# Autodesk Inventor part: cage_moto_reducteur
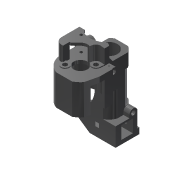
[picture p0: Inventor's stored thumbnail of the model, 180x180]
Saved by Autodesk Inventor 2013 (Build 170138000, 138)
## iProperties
Created: 2011-07
Part Number: cage_moto_reducteur
Document SubType Name: Modeling
Designer: didierf
Density: 1.13 g/cm^3
Material: Nylon - 6/6
Mass: 1.97671 g
Surface Area: 29.4498 cm^2
Volume: 1.7493 cm^3
entraxe_moteur_mobile: 6,000 mm
entraxe_mobile_roue_vis: 7,950 mm
entraxe_moteur_roue_vis: 12,000 mm
Author: didierf
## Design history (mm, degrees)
sketch "Esquisse1" dims "d1" = 12 (= 2 x entraxe_moteur_mobile), "d3" = 15.9 (= 2 x entraxe_mobile_roue_vis), "d4" = 24 (= 2 x entraxe_moteur_roue_vis)
  geometry: C1 r 2.5 at (2.847, -0.387); C2 r 0.5 at (-1.852, 3.344); C3 r 3.14 at (-9.14, 0.167); 3 further points
  constraints: 3 centre point, 3 coincident, 9 other
  dimensions: "d0" = 5 diameter of C1; "d2" = 1 diameter of C2; "d5" = 6.28 diameter of C3
sketch "Esquisse2" dims "d66" = 15.9 (= 2 x entraxe_mobile_roue_vis), "d67" = 12 (= 2 x entraxe_moteur_mobile), "d68" = 24 (= 2 x entraxe_moteur_roue_vis)
  geometry: L1 (-154.32, -14.987)-(-180.391, -5.63); L2 (-180.391, -5.63)-(-170.126, 22.971); L3 (-170.126, 22.971)-(-144.055, 13.613); L4 (-144.055, 13.613)-(-154.32, -14.987); L5 (-31.79, 28.076)-(-25.53, 28.076); L6 (-25.53, 28.076)-(-25.53, 27.076); L7 (-25.53, 27.076)-(-31.79, 27.076); L8 (-31.79, 27.076)-(-31.79, 28.076); L9 (-31.79, 28.076)-(-25.53, 27.076); L10 (-24.13, 32.056)-(-24.13, 23.306); L11 (-32.96, 32.056)-(-32.96, 23.306); L12 (-28.66, 27.576)-(-28.66, 30.706); L13 (-29.16, 24.446)-(-29.16, 30.706); L14 (-29.16, 30.706)-(-28.66, 30.706); L15 (-32.96, 32.056)-(-24.13, 32.056); L16 (-32.96, 23.306)-(-24.13, 23.306); L17 (-19.93, 38.152)-(-19.93, 8.926); L18 (-33.93, 33.977)-(-33.93, 8.926); L19 (-33.93, 8.926)-(-19.93, 8.926); L20 (-67.292, 19.43)-(-62.292, 19.43); L21 (-62.292, 19.43)-(-62.292, 18.43); L22 (-62.292, 18.43)-(-67.292, 18.43); L23 (-67.292, 18.43)-(-67.292, 19.43); L24 (-67.292, 19.43)-(-62.292, 18.43); L25 (-29.16, 24.446)-(-27.655, 24.446); C1 r 2.5 at (-60.831, 26.959); C2 r 0.5 at (-31.23, 20.052); C3 r 2.5 at (-27.128, 15.674); A1 r 3.17 centre (-28.66, 27.576) between (-31.79, 27.076) and (-29.16, 30.706); 4 further points
  constraints: 42 end point, 10 parallel, 7 perpendicular, 4 centre point, 3 coincident, 3 point on circle, 2 horizontal, 2 midpoint, 14 other
  dimensions: "d7" = 27.7 distance of L2.end L3.end; "d46" = 1 distance of L7.end L5.start; "d47" = 6.26 distance of L5.start L5.end; "d48" = 1.4 distance between parallel lines of L10 L6; "d49" = 8.83 distance between parallel lines of L11 L10; "d50" = 0.5 distance between parallel lines of L12 L13; "d51" = 1.35 distance between parallel lines of L15 L14; "d54" = 8.75 distance between parallel lines of L16 L15; "d55" = 4.2 distance between parallel lines of L17 L10; "d56" = 14 distance between parallel lines of L18 L17; "d58" = 23.13 distance between parallel lines of L19 L15; "d63" = 5 diameter of C1; "d64" = 5 distance of L21.end L22.end; "d65" = 1 distance of L20.end L21.end; "d69" = 2.7 distance from line of L18 C2.centre; "d275" = 5 diameter of C3; "d277" = 1 diameter of C2
  node "Image1"
sketch "Esquisse3"
  geometry: L1 (-32.96, 32.056)-(-24.13, 32.056) reference; L2 (-32.96, 32.056)-(-32.96, 23.306) reference; L3 (-32.96, 23.306)-(-24.13, 23.306) reference; L4 (-24.13, 32.056)-(-24.13, 23.306) reference
  dimensions: "d73" = 8.83 distance of L1.start L1.end (derived); "d74" = 8.75 distance of L1.start L2.end (derived)
extrude "corps_vis" new body sketch "Esquisse3" distance "d71" = 25.84; taper "d72" = 0 deg
sketch "Esquisse4"
  geometry: C1 r 3.175 at (-28.66, 27.576) reference
extrude "alésage roulements" cut sketch "Esquisse4" distance "d75" = 16.9; taper "d76" = 0 deg
sketch "Esquisse5"
  geometry: L1 (-24.13, 32.056)-(-24.13, 23.306) reference; L2 (-32.96, 32.056)-(-24.13, 32.056) reference; L3 (-32.96, 23.306)-(-32.96, 32.056) reference; L4 (-24.13, 23.306)-(-32.96, 23.306) reference; C1 r 3.17 at (-28.66, 27.576); C2 r 3 at (-28.66, 27.576); C3 r 3.175 at (-28.66, 27.576) reference
  constraints: 2 centre point, 1 coincident
  dimensions: "d289" = 6 diameter of C2
extrude "alésage butée roul" cut sketch "Esquisse5" distance "d79" = 19; taper "d80" = 0 deg
sketch "Esquisse6"
  geometry: L1 (-24.13, 32.056)-(-24.13, 23.306) reference; L2 (-32.96, 32.056)-(-24.13, 32.056) reference; L3 (-32.96, 23.306)-(-32.96, 32.056) reference; L4 (-24.13, 23.306)-(-32.96, 23.306) reference; C1 r 3.17 at (-28.66, 27.576); C2 r 1.98 at (-28.66, 27.576); C3 r 3.175 at (-28.66, 27.576) reference
  constraints: 2 centre point, 1 coincident
  dimensions: "d81" = 3.96 diameter of C2
extrude "alésage extrem vis" cut sketch "Esquisse6" stored distance "d82" = 19; taper "d83" = 0 deg
sketch "Esquisse9"
  geometry: L1 (0, 0)-(0, 25.84) reference; L2 (0, 25.84)-(0, 27.34); L3 (0, 27.34)-(-4, 27.34); L4 (-4, 27.34)-(-4, 0); L5 (0, 0)-(-4, 0)
  constraints: 8 end point, 2 perpendicular, 1 collinear, 1 parallel
  dimensions: "d91" = 4 distance between parallel lines of L4 L2; "d92" = 27.34 distance between parallel lines of L3 L5
extrude "platine_fixation" join sketch "Esquisse9" distance "d93" = 4; taper "d94" = 0 deg
sketch "Esquisse10"
  geometry: L1 (12.83, 0)-(4, 0) reference; L2 (2.832, -7.632)-(2.832, 0); L3 (16.832, -7.632)-(16.832, -2.75); L4 (7.552, -14.25)-(13.36, -14.25); L5 (4, 8.75)-(12.83, 8.75) reference; L6 (12.83, 8.75)-(12.83, 0) reference; L7 (12.83, 0)-(12.83, -0.757); L8 (16.832, -2.75)-(15.032, -2.75); L9 (15.032, -2.75)-(15.032, -2.227); L10 (4, 0)-(2.832, 0); L11 (9.832, -7.632)-(20.481, -7.632); L12 (16.832, -7.632)-(15.742, -12.25); C1 r 2.5 at (9.832, -7.632) reference; A1 r 7.5 centre (9.832, -7.632) between (13.36, -14.25) and (15.742, -12.25); A2 r 7 centre (9.832, -7.632) between (2.832, -7.632) and (7.552, -14.25); A3 r 7.5 centre (9.832, -7.632) between (15.032, -2.227) and (12.83, -0.757)
  constraints: 18 end point, 6 point on circle, 3 centre point, 3 perpendicular, 2 collinear, 2 parallel, 1 coincident, 1 point on line, 1 tangent
  dimensions: "d96" = 14 distance between parallel lines of L3 L2; "d97" = 23 distance between parallel lines of L4 L5; "d99" = 7.5 radius of A1; "d100" = 7 radius of A2; "d102" = 11.5 distance between parallel lines of L8 L4; "d103" = 7.5 radius of A3; "d104" = 1.8 distance between parallel lines of L3 L9; "d108" = 2 distance from line of L12.end L4
extrude "cage moteur" join sketch "Esquisse10" distance "d105" = 11.2; taper "d106" = 0 deg
sketch "Esquisse11" dims "d126" = 8
  geometry: L1 (5.232, -14.032)-(5.832, -14.032); L2 (5.832, -14.032)-(5.832, -11.632); L3 (5.832, -11.632)-(2.832, -11.632); L4 (2.832, -11.632)-(2.832, -14.032); L5 (14.332, -5.632)-(14.332, -7.321); L6 (15.032, -6.75)-(15.032, -6.227); L7 (7.552, -18.25)-(13.36, -18.25); L8 (16.832, -11.632)-(16.832, -6.75); L9 (2.832, -4)-(2.832, -11.632); L10 (5.832, -11.632)-(2.832, -11.632); L11 (12.83, -4.757)-(12.83, -4); L12 (9.832, -11.632)-(12.661, -8.803); L13 (12.834, -7.163)-(14.332, -7.321); L14 (9.773, -6.573)-(10.012, -9.138); L15 (11.045, -8.469)-(10.862, -9.354); L16 (4, 0)-(0, 0) reference; L17 (0, -4)-(0, 0) reference; L18 (2.832, -4)-(0, -4) reference; L19 (2.832, -4)-(2.832, -11.632) reference; L20 (7.552, -18.25)-(13.36, -18.25) reference; L21 (15.742, -16.25)-(16.832, -11.632) reference; L22 (16.832, -11.632)-(16.832, -6.75) reference; L23 (16.832, -6.75)-(15.032, -6.75) reference; L24 (15.032, -6.75)-(15.032, -6.227) reference; L25 (12.83, -4.757)-(12.83, -4) reference; L26 (12.83, -4)-(4, -4) reference; L27 (4, -4)-(4, 0) reference; C1 r 3.17 at (8.3, 0.27); C2 r 0.906 at (-111.833, -48.822); C3 r 0.735 at (-104.635, -44.629); C4 r 2.5 at (9.832, -11.632) reference; A1 r 2.4 centre (5.232, -11.632) between (2.832, -11.632) and (5.232, -14.032); A2 r 7.5 centre (9.832, -11.632) between (15.032, -6.227) and (12.83, -4.757); A3 r 1.65 centre (12.661, -8.803) between (12.834, -7.163) and (11.045, -8.469); A4 r 7 centre (9.832, -11.632) between (2.832, -11.632) and (5.832, -17.376); A5 r 7 centre (8.3, 0.27) between (9.773, -6.573) and (13.06, -4.862); A6 r 7.5 centre (9.832, -11.632) between (14.332, -5.632) and (13.06, -4.862); A7 r 2.5 centre (9.832, -11.632) between (10.012, -9.138) and (10.862, -9.354); A8 r 2.5 centre (9.832, -11.632) between (10.862, -9.354) and (10.012, -9.138); A9 r 7 centre (9.832, -11.632) between (2.832, -11.632) and (7.552, -18.25) reference; A10 r 7.5 centre (9.832, -11.632) between (13.36, -18.25) and (15.742, -16.25) reference; A11 r 7.5 centre (9.832, -11.632) between (15.032, -6.227) and (12.83, -4.757) reference
  constraints: 32 end point, 17 point on circle, 11 centre point, 5 coincident, 2 parallel, 2 perpendicular, 2 point on line, 2 tangent, 1 collinear, 1 horizontal, 3 other
  dimensions: "d114" = 2.5 distance between parallel lines of L8 L5; "d116" = 0 distance between parallel lines of L4 L9; "d117" = 3 distance of L2.end L3.end; "d118" = 2.4 distance of L3.end L4.end; "d119" = 2.4 distance between parallel lines of L10 L1; "d120" = 2.4 radius of A1; "d124" = 4.21821 distance between parallel lines of L1 L7; "d128" = 45 deg angle of L8 L12; "d129" = 3.3 diameter of A3; "d143" = 14 diameter of A5; "d144" = 1.68908 distance of L5.start L5.end
extrude "piliers" join sketch "Esquisse11" distance "d122" = 4.5; taper "d123" = 0 deg
sketch "Esquisse12"
  geometry: L1 (5.832, -11.632)-(6.332, -11.632); L2 (14.332, -7.321)-(12.834, -7.163) reference; L3 (5.832, -14.032)-(5.232, -14.032) reference; L4 (2.832, -11.632)-(2.832, -5.032); L5 (2.832, -5.032)-(4.832, -5.032); L6 (5.832, -11.632)-(5.832, -14.032) reference; L7 (14.332, -7.321)-(14.332, -5.632); L8 (6.332, -11.632)-(8.046, -9.882); L9 (13.06, -4.862)-(14.332, -5.632); L10 (11.045, -8.469)-(10.862, -9.354) reference; C1 r 3.17 at (8.3, 0.27) reference; A1 r 2.4 centre (5.232, -11.632) between (2.832, -11.632) and (5.232, -14.032) reference; A2 r 1.65 centre (12.661, -8.803) between (12.834, -7.163) and (11.045, -8.469) reference; A3 r 7 centre (8.3, 0.27) between (9.773, -6.573) and (13.06, -4.862) reference; A4 r 7 centre (8.3, 0.27) between (6.139, -6.388) and (13.06, -4.862); A5 r 7.5 centre (9.832, -11.632) between (14.332, -5.632) and (13.06, -4.862) reference; A6 r 2 centre (6.756, -4.486) between (4.832, -5.032) and (6.139, -6.388); A7 r 2.5 centre (9.832, -11.632) between (10.862, -9.354) and (10.012, -9.138) reference; A8 r 2.5 centre (9.832, -11.632) between (10.862, -9.354) and (8.046, -9.882); 1 further point
  constraints: 13 end point, 9 point on circle, 3 centre point, 3 tangent, 2 coincident, 1 horizontal, 1 parallel, 1 perpendicular, 1 point on line
  dimensions: "d133" = 0.5 distance of L1.start L1.end; "d137" = 9 distance between parallel lines of L5 L3; "d147" = 2 radius of A6; "d148" = 2 distance of L4.end L5.end
extrude "platine" join sketch "Esquisse12" distance "d138" = 1; taper "d139" = 0 deg
sketch "Esquisse14"
  geometry: L1 (-27.34, 0)-(-25.84, 0) reference; L2 (-25.84, 8.75)-(-25.84, 0) reference; L3 (-27.34, 0)-(-25.84, 1.1)
  constraints: 2 end point, 1 point on line
  dimensions: "d153" = 1.1 vertical distance of L1.start L3.end
extrude "chanfrein" join sketch "Esquisse14" stored distance "d154" = 1; taper "d155" = 0 deg
sketch "Esquisse13"
  geometry: L1 (0, 0)-(11.2, 0) reference; L2 (0, 0)-(0, 0.523) reference; L3 (1.5, 11.5)-(1.5, 3.85) reference; L4 (0, 0.523)-(11.2, 0.523) reference; L5 (4.45, 0.523)-(1.55, 0.523); L6 (4.45, 2.1)-(4.45, 0.523); L7 (4.45, 0)-(4.45, -0.154); L8 (1.55, 2.1)-(1.55, 0.523); L9 (1.05, 0)-(1.05, -0.345); L10 (27.34, 11.5)-(1.5, 11.5) reference; L11 (27.34, 11.5)-(27.34, 2.75) reference; L12 (27.34, 2.75)-(11.2, 2.75) reference; L13 (20.54, 2.75)-(20.54, 7.85); L14 (19.5, 7.85)-(20.54, 7.85); L15 (25.19, 10.75)-(19.5, 10.75); L16 (20.54, 2.75)-(27.34, 2.75); L17 (27.34, 2.75)-(27.34, 10.75); L18 (25.19, 10.75)-(25.19, 11.5); L19 (25.19, 11.5)-(27.34, 11.5); L20 (27.34, 11.5)-(27.34, 10.75); C1 r 0.9 at (3, 2.1); C2 r 0.9 at (19.5, 9.3); A1 r 1.45 centre (3, 2.1) between (4.45, 2.1) and (1.55, 2.1); A2 r 1.45 centre (19.5, 9.3) between (19.5, 10.75) and (19.5, 7.85)
  constraints: 26 end point, 8 point on line, 7 parallel, 5 point on circle, 5 tangent, 4 centre point, 4 collinear, 3 perpendicular, 2 coincident
  dimensions: "d149" = 2.1 distance from line of A1.centre L1; "d151" = 2.9 diameter of A1; "d152" = 1.8 diameter of C1; "d156" = 1.5 distance from line of L3 C1.centre; "d159" = 16.5 horizontal distance of C1.centre C2.centre; "d161" = 1.8 diameter of C2; "d162" = 6.8 distance between parallel lines of L13 L11; "d163" = 0.75 distance between parallel lines of L15 L10; "d164" = 1.45 radius of A2; "d263" = 2.15 distance between parallel lines of L20 L18
extrude "bossages" join sketch "Esquisse13" stored distance "d157" = 1; taper "d158" = 0 deg
sketch "Esquisse15"
  geometry: C1 r 0.8 at (3, 2.1); C2 r 0.8 at (19.5, 9.3); A1 r 1.45 centre (19.5, 9.3) between (19.5, 10.75) and (19.5, 7.85) reference; A2 r 1.45 centre (3, 2.1) between (4.45, 2.1) and (1.55, 2.1) reference
  constraints: 2 centre point, 2 coincident
  dimensions: "d165" = 1.6 diameter of C2; "d166" = 1.6 diameter of C1 (derived)
extrude "perçage bossage" cut sketch "Esquisse15" distance "d167" = 3; taper "d168" = 0 deg
sketch "Esquisse17"
  geometry: L1 (11.2, -2.618)-(2, -2.618); L2 (2, -2.618)-(2, 1.882); L3 (2, 1.882)-(11.2, 1.882); L4 (11.2, 1.882)-(11.2, -2.618); L5 (0, -6.618)-(11.2, -6.618) reference; L6 (0, 0)-(0, 4.882) reference; L7 (11.2, 0)-(11.2, 4.882) reference
  constraints: 8 end point, 2 parallel, 1 collinear, 1 horizontal, 1 perpendicular
  dimensions: "d172" = 4 distance between parallel lines of L5 L1; "d173" = 4.5 distance of L3.end L1.start; "d174" = 2 distance between parallel lines of L2 L6
extrude "fenetre log moteur" cut sketch "Esquisse17" distance "d175" = 5; taper "d176" = 0 deg
sketch "Esquisse16"
  geometry: C1 r 2.5 at (-9.832, -7.632) reference; C2 r 6.25 at (-9.832, -7.632)
  constraints: 1 centre point, 1 coincident
  dimensions: "d169" = 12.5 diameter of C2
extrude "log moteur" cut sketch "Esquisse16" distance "d170" = 10; taper "d171" = 0 deg
sketch "Esquisse18"
  geometry: L1 (-12.83, 8.75)-(-12.83, 1.1); L2 (-12.83, 1.1)-(-12.83, 0); L3 (-12.83, -0.757)-(-12.83, 0); L4 (-12.83, -0.757)-(-12.83, -0.75); L5 (-12.83, -0.75)-(-12.83, -0.75); L6 (-12.83, -0.75)-(-12.83, -0.757); L7 (-12.83, -0.757)-(-12.83, 0); L8 (-12.83, 0)-(-12.83, 5.1); L9 (-12.83, 5.1)-(-12.83, 8); L10 (-12.83, 0)-(-2.832, 0); L11 (-12.83, 8)-(-12.83, 8.75); L12 (-15.507, -10.25)-(-16.214, -10.25) reference; L13 (-15.742, -12.25)-(-16.214, -10.25) reference; L14 (-7.552, -14.25)-(-13.36, -14.25) reference; L15 (-2.832, 0)-(-2.832, -7.632) reference; L16 (-12.83, 0)-(-2.832, 0) reference; L17 (-12.83, -0.757)-(-12.83, 0) reference; L18 (-15.032, -2.75)-(-15.032, -2.227) reference; L19 (-16.832, -2.75)-(-15.032, -2.75) reference; L20 (-16.832, -5.75)-(-16.832, -2.75) reference; L21 (-16.832, -5.75)-(-15.792, -5.75) reference; C1 r 3.17 at (-8.3, 4.27); A1 r 4.75 centre (-8.3, 4.27) between (-12.83, 2.841) and (-10.381, 0); A2 r 6.25 centre (-9.832, -7.632) between (-15.507, -10.25) and (-15.792, -5.75) reference; A3 r 7.5 centre (-9.832, -7.632) between (-15.742, -12.25) and (-13.36, -14.25) reference; A4 r 7 centre (-9.832, -7.632) between (-7.552, -14.25) and (-2.832, -7.632) reference; A5 r 7.5 centre (-9.832, -7.632) between (-12.83, -0.757) and (-15.032, -2.227) reference
  constraints: 22 end point, 2 centre point, 2 point on circle, 2 point on line, 1 coincident
extrude "forme extrne 1" cut sketch "Esquisse18" stored distance "d178" = 5; taper "d179" = 0 deg
node "Plan de construction2"
sketch "Esquisse19"
  geometry: L1 (-1.168, -27.34)-(-4, -27.34) reference; L2 (-4, -27.34)-(-4, 0) reference; L3 (11.032, 0)-(-4, 0) reference; L4 (-5.57, -14.935)-(17.224, -14.935); L5 (8.83, -16.14)-(8.83, -6.8) reference; L6 (3.43, -6.833)-(3.43, -13.539); L7 (-4, -4.84)-(-4, -25.34); L8 (-3.129, -3.189)-(1.532, 0); L9 (1.532, 0)-(-4, 0); L10 (-4, -25.34)-(-4, -27.34); L11 (-4, -27.34)-(-2, -27.34); A1 r 2 centre (-2, -25.34) between (-2.649, -23.448) and (-2, -27.34); A2 r 2 centre (-2, -4.84) between (-1.688, -6.816) and (-3.484, -6.18); A3 r 9 centre (-5.57, -14.935) between (-2.649, -23.448) and (-3.484, -6.18)
  constraints: 14 end point, 10 point on circle, 8 tangent, 4 point on line, 3 centre point, 2 collinear, 2 parallel, 1 perpendicular
  dimensions: "d181" = 4 diameter of A1; "d182" = 4 diameter of A2; "d183" = 18 diameter of A3; "d184" = 20.5 distance of A2.centre A1.centre; "d185" = 5.4 distance between parallel lines of L6 L5; "d186" = 9.5 distance of L3.start L8.end
extrude "debouchage engrenage" cut sketch "Esquisse19" stored distance "d187" = 5; taper "d188" = 0 deg; taper "d254" = 0 deg
sketch "Esquisse22"
  geometry: L1 (0, -27.34)-(-2, -27.34) reference; L2 (0, -25.84)-(0, -27.34) reference; L3 (0, -22.005)-(0, -25.84) reference; L4 (0, -1.048)-(0, -7.866) reference; L5 (0, -1.048)-(-3.129, -3.189) reference; A1 r 9 centre (-5.57, -14.935) between (-2.649, -23.448) and (0, -22.005) reference; A2 r 2 centre (-2, -25.34) between (-2.649, -23.448) and (-2, -27.34) reference; A3 r 9 centre (-5.57, -14.935) between (0, -7.866) and (-3.484, -6.18) reference; A4 r 2 centre (-2, -4.84) between (-3.129, -3.189) and (-3.484, -6.18) reference
extrude "correction" cut sketch "Esquisse22" distance "d191" = 0.7; taper "d192" = 0 deg
sketch "Esquisse23"
  geometry: C1 r 1.7 at (-2, -25.34); C2 r 1.7 at (-2, -4.84); A1 r 2 centre (-2, -25.34) between (-2.649, -23.448) and (-2, -27.34) reference; A2 r 2 centre (-2, -4.84) between (-3.129, -3.189) and (-3.484, -6.18) reference
  constraints: 2 centre point, 2 coincident
  dimensions: "d193" = 3.4 diameter of C1; "d194" = 3.4 diameter of C2
extrude "bossages2" join sketch "Esquisse23" distance "d195" = 1; taper "d196" = 0 deg
sketch "Esquisse24"
  geometry: C1 r 1.7 at (0, 0) reference; C2 r 1.7 at (0, 20.5) reference; C3 r 1 at (0, 0); C4 r 1 at (0, 20.5)
  constraints: 2 centre point, 2 coincident
  dimensions: "d197" = 2 diameter of C3; "d198" = 2 diameter of C4
extrude "trous bossages2" cut sketch "Esquisse24" stored distance "d199" = 1; taper "d200" = 0 deg
sketch "Esquisse25"
  geometry: A1 r 9 centre (-3.57, -9.995) between (-0.084, -1.698) and (-1.011, -1.367) reference; A2 r 1.7 centre (0, 0) between (-0.084, -1.698) and (-1.011, -1.367) reference
extrude "correction2" cut sketch "Esquisse25" stored distance "d201" = 1; taper "d202" = 0 deg
sketch "Esquisse27"
  geometry: L1 (-32.96, 26.606)-(-32.96, 32.056); L2 (-32.96, 32.056)-(-24.13, 32.056); L3 (-32.96, 30.127)-(-32.96, 32.056); L4 (-32.96, 32.056)-(-30.88, 32.056); L5 (-32.96, 24.406)-(-28.838, 24.406) reference; L6 (-28.482, 24.406)-(-24.13, 24.406) reference; L7 (-24.13, 32.056)-(-24.13, 24.406) reference; L8 (-32.96, 32.056)-(-24.13, 32.056) reference; L9 (-32.96, 26.606)-(-32.96, 32.056) reference; L10 (-32.96, 24.406)-(-32.96, 26.606) reference; C1 r 3.17 at (-28.66, 27.576); A1 r 5 centre (-28.66, 27.576) between (-32.96, 30.127) and (-30.88, 32.056); A2 r 3.175 centre (-28.66, 27.576) between (-28.482, 24.406) and (-28.838, 24.406) reference
  constraints: 8 end point, 2 centre point, 2 point on circle, 2 point on line, 1 coincident, 1 collinear
  dimensions: "d210" = 10 diameter of A1
extrude "forme externe 2" cut sketch "Esquisse27" stored distance "d211" = 10; taper "d212" = 0 deg
node "Plan de construction3"
node "Plan de construction6"
sketch "Esquisse26"
  geometry: L1 (-30.88, 32.056)-(-24.13, 32.056); L2 (-32.96, 26.606)-(-32.96, 30.127); L3 (-27.081, 32.056)-(-24.13, 32.056); L4 (-24.13, 32.056)-(-24.13, 29.004); C1 r 3.17 at (-28.66, 27.576); A1 r 4.75 centre (-28.66, 27.576) between (-24.13, 29.004) and (-27.081, 32.056); 1 further point
  constraints: 8 end point, 2 centre point, 2 point on circle, 1 coincident, 1 collinear, 1 perpendicular, 1 point on line
  dimensions: "d206" = 9.5 diameter of A1
extrude "forme externe 3" cut sketch "Esquisse26" stored distance "d213" = 10; taper "d214" = 0 deg
sketch "Esquisse29"
  geometry: L1 (-30.88, 32.056)-(-24.13, 32.056) reference; L2 (-24.13, 32.056)-(-24.13, 24.406) reference; L3 (-24.13, 32.056)-(-26.12, 32.056); L4 (-24.13, 32.056)-(-24.13, 30.025); C1 r 3.17 at (-28.66, 27.576) reference; A1 r 4.75 centre (-28.66, 27.576) between (-24.13, 29.004) and (-27.081, 32.056) reference; A2 r 5.15 centre (-28.66, 27.576) between (-24.13, 30.025) and (-26.12, 32.056)
  constraints: 4 end point, 2 point on circle, 2 point on line, 1 centre point, 1 coincident
  dimensions: "d217" = 0.4 radial gap between concentric circles of A2 A1
extrude "forme externe 4" cut sketch "Esquisse29" stored distance "d218" = 18; taper "d219" = 0 deg
sketch "Esquisse30"
  geometry: L1 (2.48, 0)-(1.822, 0) reference; L2 (1.04, 1.28)-(0, 1.28) reference; L3 (0, 1.28)-(0, 0) reference; L4 (0.258, 0)-(0, 0) reference; A1 r 1.45 centre (1.04, -0.17) between (2.48, 0) and (1.04, 1.28) reference; A2 r 0.8 centre (1.04, -0.17) between (1.822, 0) and (0.258, 0) reference
extrude "bouchage forme externe 4" join sketch "Esquisse30" stored distance "d221" = 18; taper "d222" = 0 deg
sketch "Esquisse31"
  geometry: C1 r 1.7 at (-4.08, -25.34) reference; 2 further points
  constraints: 1 coincident, 3 other
extrude "marque éject" cut sketch "Esquisse31" stored distance "d224" = 18; taper "d225" = 0 deg
sketch "Esquisse32"
  geometry: L1 (0.784, -25.84)-(0, -25.84) reference; L2 (0, -27.34)-(-2, -27.34) reference; L3 (0, -25.84)-(-0.064, -25.84); L4 (0, -27.34)-(0, -25.84); L5 (0, -27.34)-(-2, -27.34); A1 r 2.828 centre (-2, -25.34) between (0.784, -25.84) and (0, -23.34) reference; A2 r 2 centre (-2, -25.34) between (-2, -27.34) and (-0.064, -25.84); 3 further points
  constraints: 7 end point, 2 coincident, 2 perpendicular, 2 point on circle, 2 point on line, 1 centre point, 1 tangent, 4 other
extrude "marque éject2" cut sketch "Esquisse32" stored distance "d226" = 18; taper "d227" = 0 deg
sketch "Esquisse33"
  geometry: L1 (-4.72, 0)-(-4.02, -0.7); L2 (-4.02, -0.7)-(-4.02, -5); L3 (-4.02, -5)-(-4.72, -5); L4 (-4.72, 0)-(-4.72, -5); L5 (-4.72, -11.2)-(-0.203, -11.2) reference; L6 (2.829, -11.2)-(-0.203, -11.2) reference; L7 (2.829, -11.2)-(5.278, -11.2) reference; L8 (7.48, -11.2)-(5.278, -11.2) reference; L9 (9.28, -11.2)-(7.48, -11.2) reference; L10 (9.28, -11.2)-(8.24, -11.2) reference; L11 (8.24, -11.2)-(7.955, -11.2) reference; L12 (7.955, -11.2)-(8.662, -11.2) reference; L13 (8.19, -11.2)-(8.662, -11.2) reference; L14 (5.809, -11.2)-(8.19, -11.2) reference; L15 (0, -11.2)-(5.809, -11.2) reference; L16 (-4.72, -11.2)-(0, -11.2) reference; L17 (-2.36, -11.2)-(-4.72, -11.2); L18 (-4.72, -11.2)-(-4.72, -9.637); L19 (-10.786, -18.006)-(-11.532, -18.006); A1 r 9 centre (-9.122, -12.405) between (-7.036, -21.16) and (-0.203, -11.2) reference; A2 r 5.2 centre (-9.122, -12.405) between (-4.063, -11.2) and (-4.72, -9.637)
  constraints: 14 end point, 4 perpendicular, 2 point on circle, 1 centre point, 1 coincident, 1 collinear, 1 midpoint, 1 point on line, 1 vertical
  dimensions: "d228" = 0.7 distance between parallel lines of L2 L4; "d229" = 5 distance from line of L3 L1.start; "d230" = 45 deg angle of L3 L1; "d233" = 3.8 radial gap between concentric circles of A1 A2
extrude "dégagement arrière" cut sketch "Esquisse33" stored distance "d231" = 18; taper "d232" = 0 deg
node "Plan de construction9"
  node "Plan de construction8"
sketch "Esquisse34"
  geometry: L1 (24.335, 27.576)-(24.335, 32.056); L2 (32.985, 27.576)-(32.985, 32.056); L3 (30.88, 32.056)-(26.12, 32.056) reference; L4 (32.985, 32.056)-(24.335, 32.056); C1 r 1.98 at (28.66, 27.576) reference; A1 r 4.325 centre (28.66, 27.576) between (24.335, 27.576) and (32.985, 27.576)
  constraints: 6 end point, 2 point on circle, 2 tangent, 1 centre point, 1 coincident, 1 collinear, 1 parallel, 1 perpendicular, 1 vertical
  dimensions: "d236" = 8.65 diameter of A1
extrude "ouverture1" cut sketch "Esquisse34" stored distance "d237" = 18; taper "d238" = 0 deg
node "Plan de construction11"
  node "Plan de construction10"
sketch "Esquisse35"
  geometry: L1 (26.68, 27.576)-(26.68, 32.056); L2 (30.88, 32.056)-(24.335, 32.056) reference; L3 (30.64, 32.056)-(26.68, 32.056); L4 (32.96, 27.111)-(32.96, 30.127) reference; L5 (30.64, 27.576)-(30.64, 32.056); A1 r 1.98 centre (28.66, 27.576) between (30.64, 27.576) and (26.68, 27.576) reference; A2 r 1.98 centre (28.66, 27.576) between (26.68, 27.576) and (30.386, 26.606); 4 further points; 1 other entity
  constraints: 6 end point, 4 point on circle, 3 point on line, 2 parallel, 2 tangent, 1 centre point, 1 coincident, 1 concentric, 1 horizontal alignment
extrude "ouverture2" cut sketch "Esquisse35" stored distance "d241" = 18; taper "d242" = 0 deg
sketch "Esquisse38"
  geometry: L1 (4.2, -6.15)-(0.24, -6.15) reference; L2 (4.2, -6.84)-(0.24, -6.84) reference; L3 (0.24, -6.15)-(0.24, -4.7) reference; L4 (-2.08, -3.2)-(2.22, -3.2); L5 (2.22, -6.15)-(2.22, -3.2); L6 (2.22, -6.15)-(-2.08, -6.15); L7 (-2.08, -7.866)-(-2.08, -1.048) reference; L8 (-2.08, -6.15)-(-2.08, -3.2); 2 further points
  constraints: 8 end point, 2 perpendicular, 2 point on line, 1 collinear, 1 midpoint, 1 parallel
extrude "ouverture3" cut sketch "Esquisse38" stored distance "d246" = 0.8; taper "d247" = 0 deg
sketch "Esquisse36"
  geometry: L1 (26.68, 27.576)-(26.68, 32.056) reference; L2 (26.68, 32.056)-(30.64, 32.056) reference; L3 (27.68, 32.056)-(27.68, 29.296); A1 r 1.98 centre (28.66, 27.576) between (30.64, 27.576) and (26.68, 27.576) reference; 2 further points
  constraints: 2 end point, 1 perpendicular, 1 point on circle, 1 point on line
  dimensions: "d243" = 1 distance between parallel lines of L3 L1
extrude "bouchage" join sketch "Esquisse36" distance "d244" = 0.8; taper "d245" = 0 deg
sketch "Esquisse37"
  geometry: L1 (0.24, -2.15)-(4.2, -2.15) reference; L2 (6.75, -2.15)-(6.75, -6.8) reference; L3 (2.22, -2.15)-(2.22, -6.15); L4 (5.771, -7.84)-(5.771, -6.8) reference; L5 (3.2, -6.15)-(0, -6.15) reference; L6 (2.22, -6.15)-(5.771, -6.15); L7 (5.771, -6.15)-(5.771, -6.8); L8 (6.75, -6.8)-(6.75, -2.15); L9 (6.75, -2.15)-(2.22, -2.15); L10 (5.771, -6.8)-(6.75, -6.8); 2 further points
  constraints: 13 end point, 2 parallel, 2 perpendicular, 1 collinear, 1 midpoint, 1 point on line
extrude "forme extene 5" cut sketch "Esquisse37" stored distance "d248" = 0.8; taper "d249" = 0 deg
sketch "Esquisse39"
  geometry: L1 (1.011, -0.75)-(1.011, 0) reference; L2 (0, 0)-(1.011, 0) reference; A1 r 5.15 centre (-2.54, -4.48) between (1.011, -0.75) and (0, 0) reference
extrude "forme extene 6" cut sketch "Esquisse39" stored distance "d250" = 0.8; taper "d251" = 0 deg
sketch "Esquisse40"
  geometry: L1 (5.57, 7.069)-(5.57, 8.785) reference; L2 (5.57, 8.785)-(7.65, 8.785) reference; L3 (5.57, 8.136)-(5.57, 8.785); L4 (5.57, 8.785)-(6.045, 8.785); C1 r 1 at (3.57, 10.095) reference; A1 r 2.8 centre (3.57, 10.095) between (5.57, 8.136) and (6.045, 8.785)
  constraints: 4 end point, 2 point on circle, 2 point on line, 1 centre point, 1 coincident, 1 perpendicular
  dimensions: "d252" = 5.6 diameter of A1
extrude "marque ejec 2" cut sketch "Esquisse40" stored distance "d253" = 0.8; taper "d254" = 0 deg
sketch "Esquisse41"
  geometry: L1 (21.19, 6.05)-(21.19, 10.24) reference; L2 (21.19, 11.5)-(21.19, 10.24) reference; L3 (21.19, 11.5)-(21.19, 10.75) reference; L4 (21.19, 10.75)-(21.19, 8.74) reference; L5 (21.19, 6.05)-(21.19, 8.74) reference; L6 (25.89, 9.1)-(25.89, 4.9); L7 (25.19, 10.75)-(19.5, 10.75) reference; L8 (25.89, 9.1)-(21.19, 9.1); L9 (20.54, 2.75)-(27.34, 2.75) reference; L10 (21.19, 9.1)-(21.19, 4.9); L11 (21.19, 4.9)-(25.89, 4.9); L12 (27.34, 2.75)-(27.34, 11.5) reference
  constraints: 8 end point, 3 parallel, 1 perpendicular, 1 point on line
  dimensions: "d256" = 1.65 distance between parallel lines of L7 L8; "d258" = 2.15 distance between parallel lines of L11 L9; "d264" = 1.45 distance between parallel lines of L12 L6
extrude "ouverture arriere" cut sketch "Esquisse41" distance "d259" = 4.7; taper "d260" = 0 deg
sketch "Esquisse43"
  geometry: L1 (26.088, 30.156)-(31.188, 30.156); L2 (31.188, 30.156)-(31.188, 25.056); L3 (31.188, 25.056)-(26.088, 25.056); L4 (26.088, 25.056)-(26.088, 30.156); L5 (21.928, 23.306)-(31.428, 23.306) reference; L6 (21.928, 23.306)-(21.928, 32.056) reference
  constraints: 8 end point, 2 parallel, 1 horizontal, 1 perpendicular
  dimensions: "d265" = 1.75 distance between parallel lines of L5 L3; "d266" = 4.16 distance between parallel lines of L4 L6; "d267" = 5.1 distance between parallel lines of L2 L4; "d268" = 5.1 distance between parallel lines of L1 L3
extrude "logement lateral" cut sketch "Esquisse43" distance "d269" = 1.1; taper "d270" = 0 deg
sketch "Esquisse44"
  geometry: C1 r 0.5 at (5.73, -7.253) reference; C2 r 0.5 at (5.73, -7.253)
  constraints: 1 centre point, 1 coincident
  dimensions: "d271" = 1 diameter of C2
extrude "perçage axe mobile" cut sketch "Esquisse44" stored distance "d272" = 1.1; taper "d273" = 0 deg
sketch "Esquisse45"
  geometry: L1 (5.109, 9.447)-(2.28, 6.618); L2 (2.28, 6.618)-(-1.399, 2.94); L3 (-2.048, 3.79)-(-2.048, 4.218); L4 (-4.72, 14.25)-(-4.72, 6.618) reference; L5 (-2.32, 4.218)-(-1.72, 4.218) reference; L6 (-1.72, 6.618)-(-1.72, 4.218) reference; L7 (-0.548, 5.29)-(-1.72, 5.29); L8 (0, 0)-(5.809, 0) reference; L9 (6.78, 10.929)-(6.6, 9.283); L10 (-1.72, 4.218)-(-2.32, 4.218) reference; L11 (-2.048, 4.218)-(-1.72, 4.218); L12 (-1.72, 4.218)-(-1.72, 5.29); L13 (3.493, 9.781)-(3.31, 8.896) reference; L14 (6.78, 10.929)-(5.282, 11.087) reference; A1 r 2.5 centre (2.28, 6.618) between (2.46, 9.112) and (3.31, 8.896) reference; A2 r 1.5 centre (-0.548, 3.79) between (-2.048, 3.79) and (-0.548, 5.29); A3 r 1.5 centre (5.109, 9.447) between (4.048, 8.386) and (6.6, 9.283); A4 r 2.5 centre (2.28, 6.618) between (4.048, 8.386) and (3.31, 8.896); A5 r 2.5 centre (2.28, 6.618) between (4.048, 8.386) and (3.31, 8.896); A6 r 1.65 centre (5.109, 9.447) between (5.282, 11.087) and (3.493, 9.781) reference; 6 further points
  constraints: 14 end point, 9 point on circle, 5 coincident, 4 centre point, 3 collinear, 3 midpoint, 3 tangent, 2 parallel, 2 point on line, 3 other
  dimensions: "d281" = 3 diameter of A2; "d282" = 3 diameter of A3
extrude "fixation moteur bossage" join sketch "Esquisse45" distance "d279" = 0.3; taper "d280" = 0 deg
sketch "Esquisse46"
  geometry: C1 r 0.8 at (-0.548, 3.79); C2 r 0.8 at (5.109, 9.447); A1 r 1.5 centre (-0.548, 3.79) between (-2.048, 3.79) and (-0.548, 5.29) reference; A2 r 1.5 centre (5.109, 9.447) between (4.048, 8.386) and (6.6, 9.283) reference
  constraints: 2 centre point, 2 coincident
  dimensions: "d283" = 1.6 diameter of C2; "d284" = 1.6 diameter of C1
extrude "fixation moteur trous" cut sketch "Esquisse46" stored distance "d285" = 1.1; taper "d286" = 0 deg
node "Solide1"
node "Corps solides"
node "Corps surfaciques"
node "Boucle projetée3"
node "Boucle projetée4"
node "Boucle projetée5"
node "Boucle projetée6"
node "Boucle projetée7"
node "Boucle projetée8"
node "Boucle projetée9"
node "Référence1"
other parameters: "entraxe_moteur_mobile" = 6 [user parameter; used in 2 equation terms], "entraxe_mobile_roue_vis" = 7.95 [user parameter; used in 2 equation terms], "entraxe_moteur_roue_vis" = 12 [user parameter; used in 2 equation terms], "d95" = 15, "d98" = 7.5, "d101" = 7.5, "d136" = 9, "d177" = 9.5, "d180" = -10.3, "d203" = -4.8, "d205" = -16.5, "d234" = -3.2, "d235" = -1.5, "d239" = -2.15, "d240" = -4, "d257" = 2.2
